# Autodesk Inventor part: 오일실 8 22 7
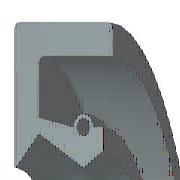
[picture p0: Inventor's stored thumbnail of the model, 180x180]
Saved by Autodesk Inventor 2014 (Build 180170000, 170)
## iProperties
IsCustomPart: 1
Created: 2012-02
Part Number: 오일실 8 22 7
Material: 고무
Description: 오일-실
Document SubType Name: Modeling
Standard: KS B 2804
Designer: mduedu
Standards Organization: KS
Language: ko-KR
Size Designation: D - 8 22 7
Categories: <MemberInstance><Categories><Category DisplayName="샤프트 부품" InternalName="7f7aeb1f-a693-4053-b835-cee3144e0d98" Mnemonic="SHFT"><Category DisplayName="실링" Intern
Density: 0.93 g/cm^3
Appearance: 고무 - 검은색 - 버전 1.1
Mass: 1.28441 g
Surface Area: 18.2787 cm^2
Volume: 1.38108 cm^3
Author: mduedu
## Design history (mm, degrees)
revolve "본체" stored, may be unused: angle "d17" = 90 deg
revolve "스프링1" stored, may be unused: angle "d18" = 90 deg
body "Solid1"
sketch "스케치1"
  geometry: L1 (0, 11)-(7, 11); L2 (7, 9.25)-(1.75, 9.25); L3 (1.75, 5.75)-(4.9, 4); L4 (4.9, 4)-(0, 4); L5 (0, 0)-(9.586, 0) reference; L6 (4.9, 4)-(6.3, 4.875); L7 (0, 18)-(0, -3) reference; L8 (-1.941, 0)-(11.507, 0) reference; L9 (4.2, 6.1)-(1.75, 6.59); L10 (1.75, 6.59)-(1.75, 9.25); L11 (0, 11)-(0, 4.088); L12 (4.9, 4)-(0, 4); L13 (1.75, 5.75)-(0.152, 4.028); L14 (7, 11)-(7, 9.25); L15 (5.6, 6.1)-(6.3, 6.1); L16 (6.3, 6.1)-(6.3, 4.875); C1 r 0.455 at (4.9, 6.1); A1 r 0.7 centre (4.9, 6.1) between (5.6, 6.1) and (4.2, 6.1); A2 r 0.088 centre (0.088, 4.088) between (0, 4.088) and (0.152, 4.028); 1 further point
  constraints: 28 end point, 5 horizontal alignment, 5 point on line, 4 point on circle, 4 vertical alignment, 3 centre point, 3 tangent, 2 collinear, 2 horizontal, 2 perpendicular, 1 coincident, 1 parallel
  dimensions: "d0" = 22 diameter of L1 L5 (= SD2); "d1" = 1.75 distance of L1.end L2.start (= SD); "d2" = 0.91 diameter of C1 (= SPDI); "d3" = 1.4 diameter of A1 (= SPDA); "d4" = 8 diameter of L3.end L5 (= NND); "d5" = 11.5 diameter of L3.start L5 (= TKDM); "d7" = 13.18 diameter of L9.end L5 (= TKDM + 0.24 x SWDT); "d8" = 1.75 distance between parallel lines of L11 L10 (= SD); "d9" = 4.9 distance from line of L11 C1.centre (= SPDST); "d10" = 12.2 diameter of C1.centre L5 (= HLDM); "d11" = 0.0875 radius of A2 (= 0.25 x LAB); "d12" = 6.3 distance between parallel lines of L11 L16 (= SDI); "d13" = 9.75 diameter of L6.end L5 (= ABDM); "d14" = 7 distance from line of L11 L1.end (= SWDT)
fillet "모깎기1" dims "d6" = 0.3 (= RR)
other parameters: "SD2" = 22 [user parameter; used in 1 equation term], "SWDT" = 7 [user parameter; used in 2 equation terms], "RR" = 0.3 [user parameter; used in 1 equation term], "SD" = 1.75 [user parameter; used in 2 equation terms], "NND" = 8 [user parameter; used in 1 equation term], "SPDA" = 1.4 [user parameter; used in 1 equation term], "SPDI" = 0.91 [user parameter; used in 1 equation term], "TKDM" = 11.5 [user parameter; used in 2 equation terms], "HLDM" = 12.2 [user parameter; used in 1 equation term], "ABDM" = 9.75 [user parameter; used in 1 equation term], "SDI" = 6.3 [user parameter; used in 1 equation term], "SPDST" = 4.9 [user parameter; used in 1 equation term], "LAB" = 0.35 [user parameter; used in 1 equation term], "d15" = 0, "d16" = 0, "d19" = 0
